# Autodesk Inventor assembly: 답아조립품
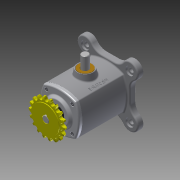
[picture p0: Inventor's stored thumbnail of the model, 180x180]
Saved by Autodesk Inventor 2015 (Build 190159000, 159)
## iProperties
Created: 2016-05
Part Number: 답아조립품
Document SubType Name: Assembly
Designer: Administrator
Author: Administrator
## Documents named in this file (11)
- C:\Users\Administrator\Desktop\460507V1006\답안조립품.iam
- C:\Users\Administrator\Desktop\460507V1006\본체.ipt
- C:\Users\Administrator\Desktop\460507V1006\베어링-6203.ipt
- C:\Users\Administrator\Desktop\460507V1006\오일실.ipt
- C:\Users\Administrator\Desktop\460507V1006\커버.ipt
- C:\Users\Administrator\Desktop\460507V1006\M4x0.7x12.ipt
- C:\Users\Administrator\Desktop\460507V1006\키5x5.ipt
- C:\Users\Administrator\Desktop\460507V1006\편심축.ipt
- C:\Users\Administrator\Desktop\460507V1006\스프로킷.ipt
- C:\Users\Administrator\Desktop\460507V1006\슬라이더.ipt
- C:\Users\Administrator\Desktop\460507V1006\부시.ipt
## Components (8 placed, 1 different names)
1. M4x0.7x12:1 — 각도:1
2. M4x0.7x12:2
3. M4x0.7x12:3
4. M4x0.7x12:4
5. M4x0.7x12:5 — 각도:2
6. M4x0.7x12:6
7. M4x0.7x12:7
8. M4x0.7x12:8
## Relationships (2: Angle 2)
- 각도:1 [Angle]: M4x0.7x12:1
- 각도:2 [Angle]: M4x0.7x12:5
